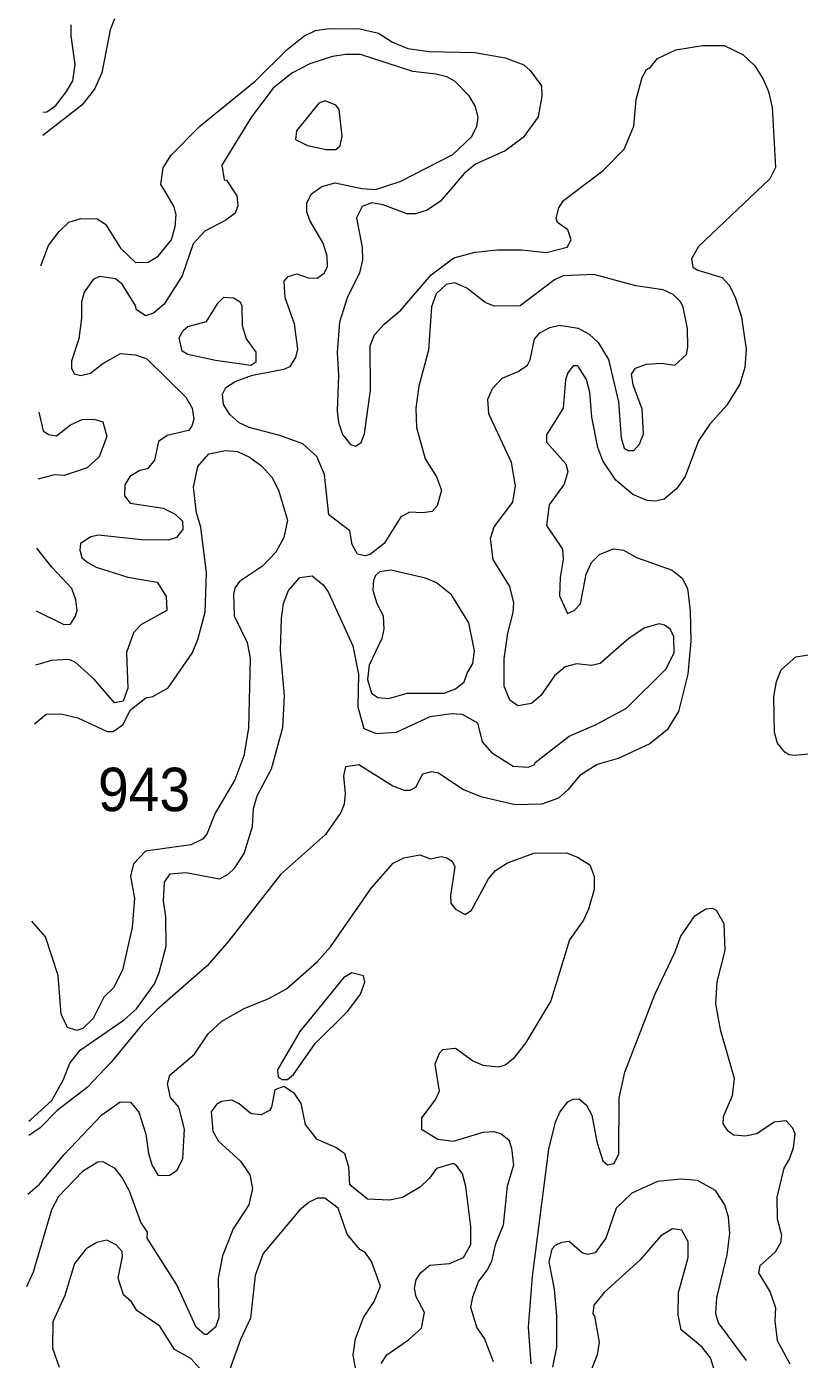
# Model space of a CAD drawing. Extents: x 763.2 to 816.8, y 7896.5 to 7952.7.
# Drawn here: x 763.671 to 766.518, y 7931.022 to 7935.931 of the extents above; entities that cross this region are included whole.
import ezdxf

# ---------------------------------------------------------------- set-up
doc = ezdxf.new("R2010")
doc.units = 0
doc.header["$LTSCALE"] = 0.064
doc.layers.add('2', color=7, linetype='Continuous', lineweight=13)
doc.layers.add('21', color=7, linetype='Continuous')

msp = doc.modelspace()

# ---------------------------------------------------------------- linework, layer by layer
at = {"layer": '2'}
for points in [[(763.9952, 7935.9604), (763.9784, 7935.9188), (763.9488, 7935.761), (763.9219, 7935.7013), (763.8751, 7935.6421), (763.7307, 7935.5304)], [(763.724, 7935.0504), (763.7524, 7935.1243), (763.7913, 7935.1766), (763.8263, 7935.211), (763.8708, 7935.224), (763.9311, 7935.2228), (763.9617, 7935.2031), (764.0176, 7935.1147), (764.0724, 7935.0624), (764.1192, 7935.0633), (764.1555, 7935.0856), (764.2045, 7935.1457), (764.2186, 7935.1945), (764.2217, 7935.2383), (764.2149, 7935.2673), (764.1835, 7935.3198), (764.166, 7935.349), (764.1745, 7935.4113), (764.2026, 7935.4566), (764.3092, 7935.5646), (764.5127, 7935.7305), (764.631, 7935.8471), (764.6919, 7935.8964), (764.7355, 7935.9167), (764.7839, 7935.9243), (764.8989, 7935.9226), (764.9674, 7935.9064), (765.0194, 7935.8739), (765.075, 7935.8507), (765.1539, 7935.8389), (765.3221, 7935.8353), (765.434, 7935.8159), (765.5031, 7935.7898), (765.5266, 7935.7697), (765.5674, 7935.7127), (765.5693, 7935.6748), (765.556, 7935.5985), (765.4998, 7935.5229), (765.4341, 7935.4738), (765.3241, 7935.4247), (765.2833, 7935.3899), (765.1958, 7935.2877), (765.1468, 7935.2545), (765.1032, 7935.2414), (765.0721, 7935.2412), (764.9851, 7935.2749), (764.9431, 7935.2816), (764.9067, 7935.269), (764.8859, 7935.2269), (764.9071, 7935.1174), (764.9085, 7935.0708), (764.8969, 7935.0248), (764.8525, 7934.9319), (764.8235, 7934.842), (764.8152, 7934.7311), (764.8199, 7934.6456), (764.8153, 7934.5153), (764.8201, 7934.4733), (764.8343, 7934.4287), (764.8641, 7934.392), (764.8825, 7934.3863), (764.9039, 7934.3998), (764.9154, 7934.4311), (764.9383, 7934.5916), (764.9368, 7934.7551), (764.9532, 7934.7953), (764.9877, 7934.8347), (765.0494, 7934.8868), (765.1613, 7935.0166), (765.245, 7935.0796), (765.3239, 7935.1008), (765.4058, 7935.1093), (765.4938, 7935.1092), (765.5859, 7935.0994), (765.6622, 7935.1183), (765.6776, 7935.1455), (765.6649, 7935.1825), (765.6272, 7935.2091), (765.6223, 7935.2258), (765.6321, 7935.2631), (765.6486, 7935.2912), (765.7949, 7935.4011), (765.8721, 7935.4796), (765.9078, 7935.5645), (765.9162, 7935.6623), (765.9387, 7935.7438), (765.9546, 7935.7734), (765.9689, 7935.7819), (765.9953, 7935.8142), (766.0625, 7935.8454), (766.1611, 7935.8618), (766.2407, 7935.8616), (766.3095, 7935.8285), (766.3542, 7935.7865), (766.3849, 7935.738)], [(763.7319, 7935.6166), (763.7455, 7935.6176), (763.7786, 7935.6409), (763.8187, 7935.6921), (763.8409, 7935.7319), (763.8503, 7935.7919), (763.8348, 7935.8972), (763.8355, 7935.9377)], [(764.7143, 7935.7942), (764.6486, 7935.7596), (764.5792, 7935.7047), (764.4996, 7935.5989), (764.3899, 7935.4204), (764.3989, 7935.3671), (764.4072, 7935.3651), (764.4455, 7935.3073), (764.4488, 7935.271), (764.4396, 7935.2444), (764.4056, 7935.2177), (764.3273, 7935.178), (764.2843, 7935.1305), (764.2438, 7935.0136), (764.178, 7934.9092), (764.1388, 7934.8761), (764.1095, 7934.8662), (764.0751, 7934.8894), (764.0734, 7934.9008), (764.0234, 7934.982), (763.9988, 7935.002), (763.9392, 7935.0104), (763.9168, 7934.9991), (763.8834, 7934.9528), (763.8735, 7934.9162), (763.8734, 7934.857), (763.8639, 7934.7812), (763.8371, 7934.6986), (763.8369, 7934.6736), (763.8459, 7934.6527), (763.8708, 7934.6458), (763.9062, 7934.6541), (763.9519, 7934.6908), (764.0167, 7934.7274), (764.072, 7934.7226), (764.1135, 7934.7069), (764.2574, 7934.5657), (764.2812, 7934.5252), (764.2873, 7934.4857), (764.2796, 7934.4592), (764.2673, 7934.4433), (764.1889, 7934.4254), (764.1565, 7934.4023), (764.1426, 7934.3338), (764.1161, 7934.3025), (764.0877, 7934.2957), (764.0511, 7934.2741), (764.033, 7934.2431), (764.0319, 7934.2029), (764.0526, 7934.176), (764.1742, 7934.1573), (764.2179, 7934.1349), (764.2449, 7934.1093), (764.2465, 7934.0789), (764.2238, 7934.0488), (764.1923, 7934.0395), (764.0943, 7934.041), (763.9359, 7934.0574), (763.9076, 7934.0521), (763.8701, 7934.0269), (763.8669, 7934.0021), (763.875, 7933.976), (763.8937, 7933.9584), (763.9274, 7933.9403), (764.0437, 7933.9032), (764.1517, 7933.8852), (764.1856, 7933.8315), (764.1879, 7933.7806), (764.0925, 7933.7274), (764.065, 7933.6987), (764.0395, 7933.6252), (764.0443, 7933.4944), (764.0275, 7933.4463), (763.9949, 7933.44), (763.9201, 7933.5276), (763.8499, 7933.5896), (763.8269, 7933.6003), (763.7624, 7933.5957), (763.7034, 7933.5792)], [(765.179, 7935.7565), (765.0935, 7935.7652), (764.9015, 7935.829), (764.847, 7935.829), (764.7977, 7935.8209), (764.7143, 7935.7942)], [(765.8726, 7934.3779), (765.8869, 7934.3699), (765.9073, 7934.3698), (765.9285, 7934.3931), (765.9434, 7934.4315), (765.9386, 7934.5214), (765.9058, 7934.6111), (765.8991, 7934.6506), (765.9136, 7934.6736), (765.955, 7934.6874), (766.0094, 7934.6917), (766.0594, 7934.684), (766.1015, 7934.7233), (766.1069, 7934.7518), (766.1051, 7934.819), (766.0901, 7934.8978), (766.0808, 7934.9161), (766.0528, 7934.9444), (766.0159, 7934.9614), (765.9155, 7934.9767), (765.7608, 7935.0186), (765.647, 7935.0133), (765.6155, 7934.9989), (765.4896, 7934.9032), (765.3932, 7934.902), (765.3603, 7934.9155), (765.2923, 7934.9673), (765.248, 7934.9871), (765.2164, 7934.9816), (765.18, 7934.9474), (765.1622, 7934.8987), (765.1519, 7934.7394), (765.1157, 7934.6073), (765.1044, 7934.5252), (765.1075, 7934.455), (765.1387, 7934.3391), (765.1812, 7934.2733), (765.1994, 7934.2234), (765.1833, 7934.1663), (765.1645, 7934.1446), (765.1305, 7934.1396), (765.083, 7934.1427), (765.0498, 7934.126), (764.9885, 7934.0275), (764.9371, 7933.9864), (764.9182, 7933.982), (764.8898, 7933.9883), (764.8709, 7934.0236), (764.8622, 7934.0742), (764.7841, 7934.1332), (764.7691, 7934.2818), (764.7408, 7934.3481), (764.6886, 7934.3942), (764.6043, 7934.4246), (764.4912, 7934.4545), (764.4547, 7934.4719), (764.4196, 7934.5023), (764.3966, 7934.5388), (764.3932, 7934.5767), (764.4049, 7934.602), (764.4389, 7934.6243), (764.5028, 7934.647), (764.6185, 7934.6696), (764.642, 7934.6797), (764.6631, 7934.7119), (764.6704, 7934.7427), (764.6585, 7934.8361), (764.6231, 7934.9327), (764.6201, 7934.993), (764.6351, 7935.0108), (764.6668, 7935.0202), (764.7083, 7935.0057), (764.7416, 7935.0045), (764.769, 7935.0237), (764.7791, 7935.0475), (764.7787, 7935.0852), (764.7641, 7935.1338), (764.7143, 7935.2173), (764.7036, 7935.2483), (764.7036, 7935.2824), (764.7208, 7935.3156), (764.7583, 7935.3428), (764.8075, 7935.3557), (764.9057, 7935.3353), (764.9564, 7935.331), (765.0478, 7935.3604), (765.2413, 7935.4597), (765.3097, 7935.5256), (765.3293, 7935.5638), (765.3344, 7935.5967), (765.3242, 7935.6373), (765.3015, 7935.6762), (765.2504, 7935.7287), (765.2196, 7935.7456), (765.179, 7935.7565)], [(766.3849, 7935.738), (766.4045, 7935.692), (766.4174, 7935.6327), (766.4303, 7935.4126), (766.4084, 7935.3704), (766.1459, 7935.1217)], [(766.1459, 7935.1217), (766.1206, 7935.0762), (766.1256, 7935.045), (766.1442, 7935.0339), (766.2333, 7935.0071), (766.26, 7934.9771), (766.2824, 7934.9308), (766.3042, 7934.8604), (766.3221, 7934.7434), (766.3169, 7934.6756), (766.2987, 7934.6139), (766.2502, 7934.5362), (766.1875, 7934.4666), (766.1455, 7934.4055), (766.0972, 7934.2734), (766.0651, 7934.2281), (766.0196, 7934.1899), (765.9868, 7934.1826), (765.9565, 7934.1858), (765.9048, 7934.2074), (765.8413, 7934.2608), (765.7935, 7934.3317), (765.7758, 7934.3803), (765.7538, 7934.4923), (765.7453, 7934.5849), (765.7334, 7934.6315), (765.7022, 7934.6815), (765.6844, 7934.6814), (765.6651, 7934.6557), (765.6566, 7934.6302), (765.6479, 7934.5252), (765.5861, 7934.4272), (765.586, 7934.3999), (765.658, 7934.321), (765.6647, 7934.2918), (765.6512, 7934.2458), (765.5963, 7934.1699), (765.5862, 7934.0938), (765.6448, 7934.0064), (765.6482, 7933.9685), (765.6369, 7933.902), (765.6337, 7933.8343), (765.6634, 7933.7692), (765.6876, 7933.7798), (765.7109, 7933.805), (765.7329, 7933.9143), (765.7519, 7933.9571), (765.7819, 7933.987), (765.8318, 7934.0079), (765.8702, 7934.0029), (765.9178, 7933.9753), (766.0493, 7933.9291), (766.0857, 7933.899), (766.1052, 7933.8609), (766.115, 7933.7796), (766.1183, 7933.6679), (766.1067, 7933.5463), (766.0725, 7933.4089), (766.0305, 7933.3405), (765.9666, 7933.2896), (765.8507, 7933.2351), (765.7732, 7933.2126), (765.7088, 7933.1726), (765.6652, 7933.1196), (765.6305, 7933.0891), (765.5694, 7933.0666), (765.4708, 7933.0649), (765.3496, 7933.0932), (765.2783, 7933.1216), (765.1889, 7933.1811), (765.1626, 7933.1862), (765.1292, 7933.178), (765.1032, 7933.1285), (765.0829, 7933.1176), (765.0627, 7933.1179), (765.0206, 7933.1338), (764.8948, 7933.2125), (764.8454, 7933.2044), (764.8382, 7933.1716), (764.8447, 7933.1051), (764.8414, 7933.0665), (764.8281, 7933.0358), (764.7724, 7932.9547), (764.606, 7932.8079), (764.4162, 7932.5641), (764.3368, 7932.4716), (764.1517, 7932.3109), (764.097, 7932.256), (763.9824, 7932.1171), (763.8937, 7932.0234), (763.7833, 7931.9389), (763.7216, 7931.8743), (763.6976, 7931.8585), (763.6792, 7931.8464)], [(763.6799, 7931.8988), (763.6857, 7931.9041), (763.7637, 7931.9757), (763.8072, 7932.0534), (763.8308, 7932.1132), (763.8691, 7932.1614), (764.0323, 7932.2734), (764.0759, 7932.3127), (764.1428, 7932.4058), (764.1597, 7932.4466), (764.1856, 7932.5445), (764.184, 7932.6522), (764.1758, 7932.7106), (764.1792, 7932.7794), (764.2004, 7932.8104), (764.2573, 7932.8149), (764.3823, 7932.7921), (764.4119, 7932.8084), (764.4385, 7932.833), (764.4732, 7932.8855), (764.5027, 7932.9843), (764.5064, 7933.0507), (764.5205, 7933.098), (764.5733, 7933.1973), (764.6145, 7933.3492), (764.621, 7933.4656), (764.6065, 7933.6344), (764.6096, 7933.7519), (764.618, 7933.8059), (764.6354, 7933.8539), (764.6773, 7933.9025), (764.7235, 7933.9075), (764.7635, 7933.8754), (764.7821, 7933.8487), (764.873, 7933.6501), (764.8939, 7933.5463), (764.8909, 7933.4256), (764.9133, 7933.3454), (764.9591, 7933.3279), (765.0338, 7933.3321), (765.1579, 7933.3898), (765.2368, 7933.4016), (765.2761, 7933.3985), (765.3325, 7933.3668), (765.3494, 7933.2967), (765.3839, 7933.257), (765.4637, 7933.2065), (765.5191, 7933.2029), (765.5427, 7933.2129), (765.5443, 7933.22), (765.6692, 7933.3174), (765.7693, 7933.3604), (765.8809, 7933.4201), (766.0274, 7933.5656), (766.0559, 7933.6253), (766.0553, 7933.6832), (766.0428, 7933.7104), (766.0204, 7933.7265), (766.0008, 7933.7316), (765.9487, 7933.7168), (765.8905, 7933.6781), (765.7836, 7933.5856), (765.7519, 7933.5775), (765.697, 7933.5839), (765.6555, 7933.5726), (765.6155, 7933.5397), (765.5656, 7933.467), (765.5304, 7933.4384), (765.4808, 7933.4298), (765.4511, 7933.4496), (765.4302, 7933.5014), (765.4298, 7933.6022), (765.4444, 7933.6969), (765.464, 7933.7725), (765.4659, 7933.8086), (765.451, 7933.8684), (765.3899, 7933.9684), (765.3805, 7934.0452), (765.3937, 7934.0886), (765.4622, 7934.18), (765.4724, 7934.2398), (765.4575, 7934.3259), (765.3741, 7934.5054), (765.3707, 7934.5586), (765.3875, 7934.5978), (765.4232, 7934.6358), (765.4813, 7934.6609), (765.5167, 7934.6841), (765.5265, 7934.7038), (765.5418, 7934.7804), (765.5613, 7934.8032), (765.5991, 7934.8232), (765.6341, 7934.8317), (765.7029, 7934.8204), (765.7436, 7934.7984)], [(765.7436, 7934.7984), (765.776, 7934.7677), (765.8141, 7934.7047), (765.852, 7934.5488), (765.8608, 7934.4161), (765.8726, 7934.3779)], [(763.7164, 7934.5113), (763.7328, 7934.4416), (763.7524, 7934.4292), (763.7812, 7934.4243), (763.8334, 7934.4645), (763.8753, 7934.4844), (763.9187, 7934.4846), (763.9524, 7934.4758), (763.9669, 7934.4212), (763.9383, 7934.3464), (763.8937, 7934.306), (763.8101, 7934.2779), (763.7734, 7934.2807), (763.713, 7934.2644)], [(763.7004, 7933.363), (763.7428, 7933.3982), (763.7978, 7933.3999), (763.8597, 7933.3854), (763.9675, 7933.3349), (763.9899, 7933.3345), (764.0275, 7933.3601), (764.0527, 7933.413), (764.1107, 7933.4589), (764.1358, 7933.4639), (764.193, 7933.4951), (764.281, 7933.6228), (764.3014, 7933.6734), (764.3288, 7933.7745), (764.3334, 7933.919), (764.3124, 7934.0874), (764.2976, 7934.1406), (764.2861, 7934.2345), (764.3019, 7934.3109), (764.3429, 7934.3575), (764.4033, 7934.3696), (764.4486, 7934.3661), (764.4918, 7934.3447), (764.5362, 7934.3129), (764.5746, 7934.2716), (764.5994, 7934.2241), (764.6326, 7934.1137), (764.6192, 7934.0487), (764.5891, 7933.9956), (764.5405, 7933.9443), (764.4554, 7933.8867), (764.439, 7933.8649), (764.4327, 7933.8415), (764.4354, 7933.7606), (764.4837, 7933.6623), (764.4946, 7933.6048), (764.488, 7933.3465), (764.4714, 7933.2456), (764.4378, 7933.1565), (764.3661, 7933.0339), (764.3351, 7932.9561), (764.3193, 7932.9381), (764.2764, 7932.9177), (764.1089, 7932.8937), (764.0649, 7932.8478), (764.0544, 7932.8015), (764.0688, 7932.7193), (764.0605, 7932.6122), (764.0246, 7932.4557), (763.9908, 7932.3904), (763.9558, 7932.3564), (763.9167, 7932.2772), (763.8784, 7932.2406), (763.8558, 7932.2332), (763.8216, 7932.2446), (763.7987, 7932.2936), (763.7878, 7932.4353), (763.7414, 7932.5784), (763.6902, 7932.6356)], [(763.7062, 7933.7796), (763.8084, 7933.7288), (763.8326, 7933.7297), (763.8516, 7933.7593), (763.857, 7933.7803), (763.8531, 7933.82), (763.8372, 7933.8618), (763.7638, 7933.9402), (763.7094, 7934.0103)], [(766.5491, 7933.2506), (766.5023, 7933.2457), (766.479, 7933.2493), (766.4636, 7933.2587), (766.4375, 7933.2918), (766.426, 7933.3312), (766.4239, 7933.4628), (766.4335, 7933.5186), (766.4501, 7933.562), (766.505, 7933.6097), (766.6553, 7933.6329)], [(763.6761, 7931.6309), (763.7183, 7931.6672), (763.8089, 7931.7757), (763.9479, 7931.923), (764.0162, 7931.9702), (764.0533, 7931.969), (764.085, 7931.9327), (764.1105, 7931.8514), (764.1203, 7931.7801), (764.134, 7931.7365), (764.1561, 7931.6993), (764.1974, 7931.7003), (764.2261, 7931.7183), (764.2463, 7931.7614), (764.2529, 7931.87), (764.2321, 7931.9508), (764.2016, 7931.9871), (764.1907, 7932.037), (764.199, 7932.0687), (764.2896, 7932.1466), (764.3406, 7932.2206), (764.39, 7932.2681), (764.4722, 7932.3139), (764.5637, 7932.3517), (764.6288, 7932.3874), (764.7416, 7932.4867), (764.7908, 7932.5411), (764.9412, 7932.7585), (765.0211, 7932.8492), (765.0607, 7932.8694), (765.1191, 7932.8807), (765.1588, 7932.866), (765.1979, 7932.8738), (765.217, 7932.8708), (765.2384, 7932.8571), (765.2487, 7932.8361), (765.2326, 7932.7311), (765.2341, 7932.7029), (765.251, 7932.6799), (765.2867, 7932.6607), (765.3101, 7932.6763), (765.3727, 7932.7925), (765.3988, 7932.823), (765.4423, 7932.8507), (765.54, 7932.8871), (765.6594, 7932.8877), (765.7009, 7932.8724), (765.7463, 7932.8431), (765.762, 7932.802), (765.762, 7932.7531), (765.7408, 7932.6799), (765.7225, 7932.6398), (765.6715, 7932.5678), (765.6019, 7932.3428), (765.509, 7932.1861), (765.4631, 7932.1285), (765.4345, 7932.1058), (765.4078, 7932.0985), (765.3525, 7932.105), (765.3141, 7932.1218), (765.2512, 7932.1669), (765.2031, 7932.1622), (765.1906, 7932.149), (765.1751, 7932.1093), (765.1913, 7932.0102), (765.1782, 7931.9818), (765.1258, 7931.9112), (765.126, 7931.8702), (765.1859, 7931.8334), (765.2435, 7931.8257), (765.3526, 7931.8583), (765.3926, 7931.8615), (765.4198, 7931.8525), (765.4473, 7931.8307), (765.4579, 7931.8002), (765.4645, 7931.7374), (765.4413, 7931.6596), (765.4267, 7931.516), (765.3972, 7931.4434), (765.3832, 7931.3822), (765.368, 7931.3518), (765.3355, 7931.3099), (765.3131, 7931.2513), (765.3067, 7931.214), (765.3293, 7931.1377), (765.3576, 7931.097), (765.3903, 7931.0145)], [(765.6652, 7931.9707), (765.6845, 7931.98), (765.707, 7931.9816), (765.7341, 7931.9581), (765.7535, 7931.9216), (765.7718, 7931.8234), (765.7934, 7931.7534), (765.8111, 7931.7389), (765.8349, 7931.7435), (765.8521, 7931.7794), (765.8538, 7931.9843), (765.8742, 7932.0802), (765.9863, 7932.3683), (766.0589, 7932.5202), (766.0809, 7932.5805), (766.1332, 7932.6552), (766.1732, 7932.6818), (766.1976, 7932.6834), (766.2106, 7932.6762), (766.2397, 7932.6269), (766.2432, 7932.528), (766.2139, 7932.413), (766.2088, 7932.332), (766.2262, 7932.2371), (766.2775, 7932.058), (766.2698, 7931.9926), (766.2366, 7931.9154), (766.2354, 7931.8894), (766.2522, 7931.8662), (766.2759, 7931.8491), (766.3188, 7931.8454), (766.3615, 7931.8536), (766.4247, 7931.8964), (766.4672, 7931.9012), (766.4925, 7931.875), (766.5012, 7931.8521), (766.4949, 7931.8016), (766.4817, 7931.7622), (766.4603, 7931.7257), (766.4343, 7931.6192), (766.4356, 7931.5395), (766.4517, 7931.4795), (766.4487, 7931.4515), (766.4281, 7931.4172), (766.372, 7931.3659), (766.3668, 7931.3408), (766.4098, 7931.2699), (766.4299, 7931.2115), (766.4274, 7931.1639), (766.4356, 7931.0911), (766.4823, 7931.0053)], [(764.9778, 7931.0065), (764.9986, 7931.0391), (765.0783, 7931.094), (765.1253, 7931.1371), (765.1372, 7931.195), (765.1061, 7931.2521), (765.0996, 7931.2836), (765.106, 7931.3154), (765.1226, 7931.3407), (765.156, 7931.3685), (765.229, 7931.3756), (765.2808, 7931.3974), (765.3077, 7931.4454), (765.3081, 7931.5108), (765.2896, 7931.6585), (765.2772, 7931.705), (765.2544, 7931.7363), (765.2429, 7931.743), (765.1807, 7931.7253), (765.1553, 7931.6893), (765.1203, 7931.6557), (765.0554, 7931.6181), (765.0081, 7931.6088), (764.9266, 7931.6117), (764.8615, 7931.6643), (764.8577, 7931.7293), (764.8429, 7931.7792), (764.8108, 7931.8022), (764.7414, 7931.8319), (764.6983, 7931.8871), (764.682, 7931.9646), (764.6577, 7932.0008), (764.6189, 7932.0275), (764.5858, 7932.0151), (764.5735, 7931.9512), (764.5659, 7931.9388), (764.5356, 7931.9222), (764.4983, 7931.9261), (764.4547, 7931.9626)], [(764.4547, 7931.9626), (764.427, 7931.9766), (764.3895, 7931.9718), (764.3703, 7931.961), (764.3505, 7931.934), (764.3572, 7931.8621)], [(765.5202, 7931.141), (765.535, 7931.3276), (765.5945, 7931.7967), (765.6196, 7931.8953), (765.6352, 7931.9324), (765.6652, 7931.9707)], [(764.3572, 7931.8621), (764.378, 7931.8258), (764.4591, 7931.7526), (764.4931, 7931.7017), (764.5027, 7931.6517), (764.4899, 7931.5914), (764.4326, 7931.5025), (764.3928, 7931.4032), (764.3764, 7931.3205), (764.3797, 7931.1746), (764.3667, 7931.1411), (764.3349, 7931.1132), (764.3261, 7931.1136), (764.2962, 7931.1404), (764.2247, 7931.2962), (764.1153, 7931.468), (764.116, 7931.491), (764.0919, 7931.5271), (764.0498, 7931.6419), (764.0232, 7931.6919), (763.997, 7931.7247), (763.953, 7931.7497), (763.9336, 7931.7489), (763.8768, 7931.7137), (763.789, 7931.6223), (763.7629, 7931.5728), (763.6956, 7931.3435), (763.6714, 7931.2888)], [(766.3227, 7931.0173), (766.2203, 7931.1568), (766.2105, 7931.1893), (766.2142, 7931.2491), (766.2514, 7931.4072), (766.2613, 7931.4861), (766.2562, 7931.546), (766.2432, 7931.5916), (766.2088, 7931.6443), (766.1421, 7931.6807), (766.0815, 7931.6859), (765.995, 7931.6776), (765.9003, 7931.6337), (765.8424, 7931.5786), (765.8053, 7931.4678), (765.7652, 7931.414), (765.7375, 7931.4082), (765.7174, 7931.4149)], [(764.885, 7930.977), (764.8743, 7931.0377), (764.8825, 7931.097), (764.9119, 7931.1758), (764.9511, 7931.2351), (764.9745, 7931.2911), (764.9415, 7931.3819), (764.9195, 7931.4139), (764.8986, 7931.427), (764.8516, 7931.4828), (764.8194, 7931.5791), (764.7698, 7931.6151), (764.7427, 7931.6151), (764.7125, 7931.6005), (764.6769, 7931.5719), (764.5424, 7931.4114), (764.5128, 7931.3309), (764.4962, 7931.1733), (764.4587, 7931.095), (764.4186, 7930.9816)], [(766.2038, 7930.9851), (766.1909, 7931.0278), (766.1589, 7931.0685), (766.0826, 7931.1307), (766.0708, 7931.1864), (766.0723, 7931.2678), (766.1084, 7931.3968), (766.1085, 7931.455), (766.085, 7931.4981), (766.0506, 7931.5032), (766.0068, 7931.4771), (765.9315, 7931.389), (765.7984, 7931.2688), (765.7604, 7931.2219), (765.7571, 7931.1903), (765.7634, 7931.1815), (765.7797, 7931.0851), (765.7734, 7931.0391), (765.7453, 7930.9695)], [(763.9293, 7931.4524), (763.8904, 7931.4285), (763.8474, 7931.3749), (763.8121, 7931.2573), (763.7684, 7931.1602), (763.767, 7931.0633), (763.7911, 7930.9931)], [(764.0082, 7931.3212), (764.0245, 7931.4006), (764.023, 7931.419), (764.0014, 7931.4444), (763.9673, 7931.4607), (763.9293, 7931.4524)], [(765.7174, 7931.4149), (765.6699, 7931.4556), (765.642, 7931.4523), (765.6186, 7931.4419), (765.6053, 7931.4284), (765.5942, 7931.3806)], [(765.5942, 7931.3806), (765.6139, 7931.281), (765.6236, 7931.1824), (765.6234, 7931.0671), (765.6077, 7930.9938)], [(764.3096, 7930.9883), (764.2763, 7931.0249), (764.2158, 7931.0577), (764.1621, 7931.1439), (764.0767, 7931.2019), (764.0576, 7931.2334), (764.0285, 7931.2598), (764.0082, 7931.3212)], [(765.53, 7931.0055), (765.5202, 7931.141)]]:
    msp.add_lwpolyline(points, dxfattribs=at)
for points in [[(764.8226, 7935.6255), (764.8104, 7935.6424), (764.7707, 7935.6581), (764.7479, 7935.6496), (764.6649, 7935.5475), (764.6612, 7935.5149), (764.7057, 7935.4936), (764.7747, 7935.4789), (764.8108, 7935.478), (764.8268, 7935.4914), (764.8331, 7935.527)], [(764.2483, 7934.8118), (764.2645, 7934.8263), (764.3339, 7934.8453), (764.3764, 7934.9134), (764.398, 7934.9347), (764.4339, 7934.9325), (764.4578, 7934.917), (764.4642, 7934.9031), (764.4651, 7934.8299), (764.4803, 7934.7816), (764.5159, 7934.7321), (764.516, 7934.6957), (764.4966, 7934.6824), (764.3666, 7934.7007), (764.2647, 7934.7232), (764.2447, 7934.7355), (764.2335, 7934.7849)], [(765.2999, 7933.7345), (765.2366, 7933.8376), (765.1812, 7933.8823), (765.1408, 7933.8999), (765.0129, 7933.9288), (764.9714, 7933.9223), (764.9567, 7933.9092), (764.9484, 7933.8907), (764.9466, 7933.8558), (764.9598, 7933.8093), (764.9842, 7933.7599), (764.9876, 7933.7113), (764.9791, 7933.6772), (764.9334, 7933.5785), (764.9271, 7933.526), (764.942, 7933.4759), (764.9653, 7933.4594), (765.0053, 7933.4561), (765.0731, 7933.4755), (765.2096, 7933.4757), (765.251, 7933.4919), (765.2834, 7933.5173), (765.2935, 7933.5497), (765.3148, 7933.5854), (765.321, 7933.6324)], [(764.8541, 7932.3043), (764.9008, 7932.367), (764.917, 7932.4108), (764.912, 7932.4346), (764.8691, 7932.4463), (764.8379, 7932.4269), (764.6779, 7932.2296), (764.595, 7932.0887), (764.5973, 7932.0621), (764.613, 7932.0527), (764.6319, 7932.0526), (764.6545, 7932.0712), (764.7335, 7932.186)]]:
    msp.add_lwpolyline(points, close=True, dxfattribs=at)

# ---------------------------------------------------------------- texts
at = {"layer": '21', "width": 0.95}
msp.add_text('943', height=0.16, dxfattribs=at).set_placement((763.9343, 7933.0413))

doc.saveas('drawing.dxf')
